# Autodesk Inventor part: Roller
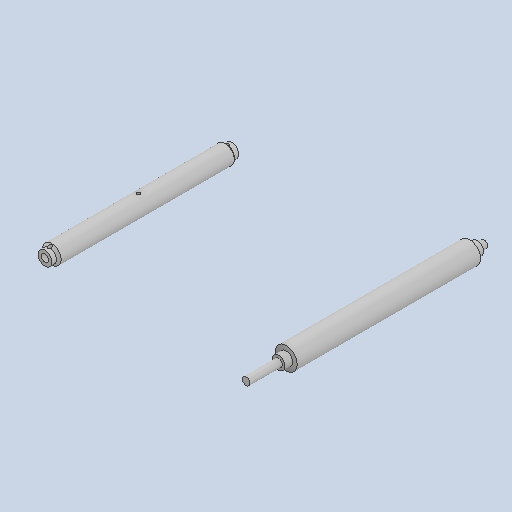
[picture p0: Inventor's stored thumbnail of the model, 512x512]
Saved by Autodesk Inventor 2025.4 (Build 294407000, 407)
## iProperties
Created: 2026-06
Part Number: Roller
Material: Generic
Document SubType Name: Modeling
Designer: AdminForWorker
Density: 1 g/cm^3
Appearance: Default
Title: Roller v4
Author: AdminForWorker
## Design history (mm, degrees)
feature "Roller Avant" [Body]
feature "Body2"
body "Solid1"
body "Solid2"
